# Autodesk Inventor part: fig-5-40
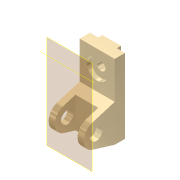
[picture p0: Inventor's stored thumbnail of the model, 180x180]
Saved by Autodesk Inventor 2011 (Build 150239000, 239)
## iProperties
Shininess: 65.0
Angle Display Precision: 2
Document Length Units: 11269
Document Angle Units: 11279
Document Time Units: 11290
Document Mass Units: 11283
Document Length Units Precision: 3
Document Angle Units Precision: 2
Created: 2001-11
Part Number: fig-5-40
Document SubType Name: Modeling
Designer: Renu Muthoo
Density: 1 g/cm^3
Density: 0.0
Volumn: 0.0
Area: 0.0
PropertySet Name: Model Information
Control State: 0
Master: False
Checked Out: False
Author: Renu Muthoo
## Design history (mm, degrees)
node "Sketch1"
sketch "Sketch2"
  geometry: L1 (33.257, 104.664)-(33.257, -75.336); L2 (33.257, -75.336)-(8.257, -75.336); L3 (8.257, -75.336)-(-45.451, -59.045); L4 (-45.451, -1.628)-(8.257, 14.664); L5 (8.257, 14.664)-(8.257, 104.664); L6 (8.257, 104.664)-(33.257, 104.664); C1 r 15 at (-36.743, -30.336); A1 r 30 centre (-36.743, -30.336) between (-45.451, -1.628) and (-45.451, -59.045)
  constraints: 12 end point, 2 centre point, 2 equal length, 2 parallel, 2 point on circle, 2 tangent, 1 coincident, 1 perpendicular, 1 vertical
  dimensions: "d0" = 180 distance of L1.start L1.end; "d1" = 30 radius of A1; "d2" = 25 distance of L5.end L1.start; "d3" = 45 distance from line of L2 A1.centre; "d4" = 70 distance from line of L1 A1.centre; "d5" = 30 diameter of C1
extrude "Extrusion1" new body sketch "Sketch2" distance "d6" = 85; taper "d7" = 0 deg
workplane "Work Plane1"
sketch "Sketch3"
  geometry: L1 (15, 62.364)-(70, 62.364); L2 (70, 62.364)-(70, -52.386); L3 (70, -52.386)-(15, -52.386); L4 (15, -52.386)-(15, 62.364); L5 (0, -45)-(0, -28.708) reference
  constraints: 8 end point, 2 parallel, 1 horizontal, 1 perpendicular
  dimensions: "d8" = 55 distance of L1.start L1.end; "d9" = 15 distance between parallel lines of L5 L4
extrude "Extrusion2" cut sketch "Sketch3" distance "d10" = 50; taper "d11" = 0 deg
sketch "Sketch4"
  geometry: L1 (0, 25)-(85, 25) reference; L2 (0, 0)-(0, 25) reference; L3 (20, 25)-(65, 25); L4 (65, 25)-(65, 35); L5 (65, 35)-(20, 35); L6 (20, 35)-(20, 25)
  constraints: 8 end point, 2 parallel, 1 horizontal, 1 perpendicular, 1 point on line
  dimensions: "d12" = 45 distance of L4.end L5.end; "d13" = 10 distance of L3.end L4.end; "d14" = 20 distance between parallel lines of L2 L6
extrude "Extrusion3" join sketch "Sketch4" stored distance "d15" = 50; taper "d16" = 0 deg
sketch "Sketch5"
  geometry: L1 (85, 0)-(85, 90) reference; L2 (0, 90)-(85, 90) reference; 1 further point
  dimensions: "d17" = 42 distance from line of L2 point (42.5, 48); "d18" = 42.5 distance from line of L1 point (42.5, 48)
hole "Hole1" sketch "Sketch5" at (42.5, 48) diameter "d19" = 20; stored, may be unused: countersink angle "d23" = 82 deg, drill point angle "d25" = 118 deg; dims "d20" = 6, "d21" = 50, "d22" = 10, "d24" = 8
workaxis "Work Axis1"
  workplane "Work Plane3"
body "Solid1"
